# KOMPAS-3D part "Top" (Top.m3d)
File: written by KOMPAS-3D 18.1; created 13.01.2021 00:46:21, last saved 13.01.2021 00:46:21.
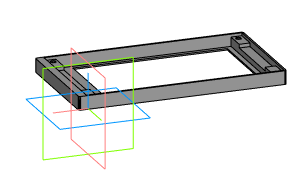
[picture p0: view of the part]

Document properties: Полное имя файла: G:\Top.m3d

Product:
- Part/product: Top

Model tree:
1. Операция без истории:1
